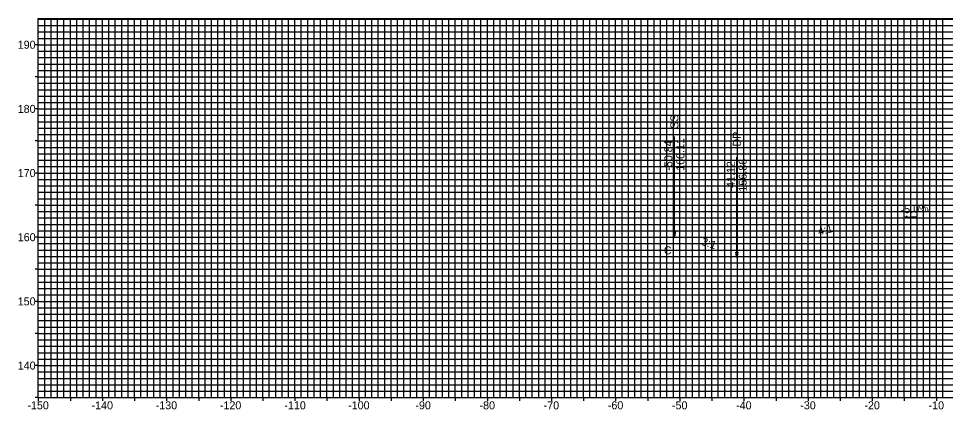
# Model space of a CAD drawing. Extents: x -153 to 153, y 133 to 194.
# Drawn here: x -153.1 to -8.6, y 133.2 to 194.1 of the extents above; entities that cross this region are included whole.
import ezdxf

# ---------------------------------------------------------------- set-up
doc = ezdxf.new("R2010")
doc.units = 0
for name, color, linetype in [('P_NCDOT_XS_Label_Grade_Point', 7, 'Continuous'), ('P_NCDOT_XS_Label_Grading_Side_Slope', 7, 'Continuous'), ('P_NCDOT_XS_Leader_Line', 7, 'Continuous'), ('P_NCDOT_XS_Sheet_Annotation_Label', 7, 'Continuous'), ('P_NCDOT_XS_Sheet_Grid_Border', 7, 'Continuous'), ('P_NCDOT_XS_Slope_Label', 7, 'Continuous'), ('P_RDY_XS_EOT_Tick_Mark', 7, 'Continuous'), ('Prop XS Label Slope Superelevation', 7, 'Continuous'), ('Sheet_Grid_Major', 7, 'Continuous'), ('Sheet_Grid_Middle', 7, 'Continuous'), ('Sheet_Grid_Minor', 7, 'Continuous')]:
    doc.layers.add(name, color=color, linetype=linetype)

msp = doc.modelspace()

# ---------------------------------------------------------------- linework, layer by layer
at = {"layer": 'P_NCDOT_XS_Leader_Line'}
for p, q in [((-50.84, 160.11), (-50.84, 175.71)), ((-41.12, 156.86), (-41.12, 172.46)), ((-41.12, 156.86), (-41.12, 172.46)), ((-50.84, 160.11), (-50.84, 169.23)), ((-41.12, 156.86), (-41.12, 165.98)), ((-41.12, 156.86), (-41.12, 165.98)), ((-50.84, 160.11), (-50.84, 161.55)), ((-41.12, 156.86), (-41.12, 158.3)), ((-41.12, 156.86), (-41.12, 158.3))]:
    msp.add_line(p, q, dxfattribs=at)
for points in [[(-50.84, 160.11), (-51.02, 160.93), (-50.67, 160.93)], [(-50.84, 160.11), (-51.02, 160.93), (-50.67, 160.93)], [(-50.84, 160.11), (-50.93, 160.52), (-50.75, 160.52)], [(-41.12, 156.86), (-41.29, 157.69), (-40.94, 157.69)], [(-41.12, 156.86), (-41.29, 157.69), (-40.94, 157.69)], [(-41.12, 156.86), (-41.29, 157.69), (-40.94, 157.69)], [(-41.12, 156.86), (-41.29, 157.69), (-40.94, 157.69)], [(-41.12, 156.86), (-41.21, 157.28), (-41.03, 157.28)], [(-41.12, 156.86), (-41.21, 157.28), (-41.03, 157.28)]]:
    msp.add_lwpolyline(points, close=True, dxfattribs=at)
at = {"layer": 'P_NCDOT_XS_Sheet_Grid_Border'}
for p, q in [((-150, 194.09), (150, 194.09)), ((-150, 135), (-150, 194.09)), ((-150, 135), (150, 135))]:
    msp.add_line(p, q, dxfattribs=at)
at = {"layer": 'P_RDY_XS_EOT_Tick_Mark'}
msp.add_line((-12, 163), (-12, 163.63), dxfattribs=at)
at = {"layer": 'Prop XS Label Slope Superelevation'}
for p, q in [((-14.9, 163.1), (-14.57, 163.36)), ((-13.1, 163.19), (-14.9, 163.1))]:
    msp.add_line(p, q, dxfattribs=at)
at = {"layer": 'Sheet_Grid_Major'}
for p, q in [((-140, 135), (-140, 194.09)), ((-130, 135), (-130, 194.09)), ((-120, 135), (-120, 194.09)), ((-110, 135), (-110, 194.09)), ((-100, 135), (-100, 194.09)), ((-90, 135), (-90, 194.09)), ((-80, 135), (-80, 194.09)), ((-70, 135), (-70, 194.09)), ((-60, 135), (-60, 194.09)), ((-50, 135), (-50, 194.09)), ((-40, 135), (-40, 194.09)), ((-30, 135), (-30, 194.09)), ((-20, 135), (-20, 194.09)), ((-10, 135), (-10, 194.09)), ((-150, 190), (150, 190)), ((-150, 180), (150, 180)), ((-150, 170), (150, 170)), ((-150, 160), (150, 160)), ((-150, 150), (150, 150)), ((-150, 140), (150, 140))]:
    msp.add_line(p, q, dxfattribs=at)
at = {"layer": 'Sheet_Grid_Middle'}
for p, q in [((-145, 135), (-145, 194.09)), ((-140, 135), (-140, 194.09)), ((-135, 135), (-135, 194.09)), ((-130, 135), (-130, 194.09)), ((-125, 135), (-125, 194.09)), ((-120, 135), (-120, 194.09)), ((-115, 135), (-115, 194.09)), ((-110, 135), (-110, 194.09)), ((-105, 135), (-105, 194.09)), ((-100, 135), (-100, 194.09)), ((-95, 135), (-95, 194.09)), ((-90, 135), (-90, 194.09)), ((-85, 135), (-85, 194.09)), ((-80, 135), (-80, 194.09)), ((-75, 135), (-75, 194.09)), ((-70, 135), (-70, 194.09)), ((-65, 135), (-65, 194.09)), ((-60, 135), (-60, 194.09)), ((-55, 135), (-55, 194.09)), ((-50, 135), (-50, 194.09)), ((-45, 135), (-45, 194.09)), ((-40, 135), (-40, 194.09)), ((-35, 135), (-35, 194.09)), ((-30, 135), (-30, 194.09)), ((-25, 135), (-25, 194.09)), ((-20, 135), (-20, 194.09)), ((-15, 135), (-15, 194.09)), ((-10, 135), (-10, 194.09)), ((-150, 190), (-150.48, 190)), ((-150, 190), (150, 190)), ((-150, 185), (-150.48, 185)), ((-150, 185), (150, 185)), ((-150, 180), (-150.48, 180)), ((-150, 180), (150, 180)), ((-150, 175), (-150.48, 175)), ((-150, 175), (150, 175)), ((-150, 170), (-150.48, 170)), ((-150, 170), (150, 170)), ((-150, 165), (-150.48, 165)), ((-150, 165), (150, 165)), ((-150, 160), (-150.48, 160)), ((-150, 160), (150, 160)), ((-150, 155), (-150.48, 155)), ((-150, 155), (150, 155)), ((-150, 150), (-150.48, 150)), ((-150, 150), (150, 150)), ((-150, 145), (-150.48, 145)), ((-150, 145), (150, 145)), ((-150, 140), (-150.48, 140)), ((-150, 140), (150, 140)), ((-150, 135), (-150.48, 135)), ((-150, 135), (-150, 134.52)), ((-145, 135), (-145, 134.52)), ((-140, 135), (-140, 134.52)), ((-135, 135), (-135, 134.52)), ((-130, 135), (-130, 134.52)), ((-125, 135), (-125, 134.52)), ((-120, 135), (-120, 134.52)), ((-115, 135), (-115, 134.52)), ((-110, 135), (-110, 134.52)), ((-105, 135), (-105, 134.52)), ((-100, 135), (-100, 134.52)), ((-95, 135), (-95, 134.52)), ((-90, 135), (-90, 134.52)), ((-85, 135), (-85, 134.52)), ((-80, 135), (-80, 134.52)), ((-75, 135), (-75, 134.52)), ((-70, 135), (-70, 134.52)), ((-65, 135), (-65, 134.52)), ((-60, 135), (-60, 134.52)), ((-55, 135), (-55, 134.52)), ((-50, 135), (-50, 134.52)), ((-45, 135), (-45, 134.52)), ((-40, 135), (-40, 134.52)), ((-35, 135), (-35, 134.52)), ((-30, 135), (-30, 134.52)), ((-25, 135), (-25, 134.52)), ((-20, 135), (-20, 134.52)), ((-15, 135), (-15, 134.52)), ((-10, 135), (-10, 134.52))]:
    msp.add_line(p, q, dxfattribs=at)
at = {"layer": 'Sheet_Grid_Minor'}
for p, q in [((-150, 194), (150, 194)), ((-149, 135), (-149, 194.09)), ((-148, 135), (-148, 194.09)), ((-147, 135), (-147, 194.09)), ((-146, 135), (-146, 194.09)), ((-144, 135), (-144, 194.09)), ((-143, 135), (-143, 194.09)), ((-142, 135), (-142, 194.09)), ((-141, 135), (-141, 194.09)), ((-139, 135), (-139, 194.09)), ((-138, 135), (-138, 194.09)), ((-137, 135), (-137, 194.09)), ((-136, 135), (-136, 194.09)), ((-134, 135), (-134, 194.09)), ((-133, 135), (-133, 194.09)), ((-132, 135), (-132, 194.09)), ((-131, 135), (-131, 194.09)), ((-129, 135), (-129, 194.09)), ((-128, 135), (-128, 194.09)), ((-127, 135), (-127, 194.09)), ((-126, 135), (-126, 194.09)), ((-124, 135), (-124, 194.09)), ((-123, 135), (-123, 194.09)), ((-122, 135), (-122, 194.09)), ((-121, 135), (-121, 194.09)), ((-119, 135), (-119, 194.09)), ((-118, 135), (-118, 194.09)), ((-117, 135), (-117, 194.09)), ((-116, 135), (-116, 194.09)), ((-114, 135), (-114, 194.09)), ((-113, 135), (-113, 194.09)), ((-112, 135), (-112, 194.09)), ((-111, 135), (-111, 194.09)), ((-109, 135), (-109, 194.09)), ((-108, 135), (-108, 194.09)), ((-107, 135), (-107, 194.09)), ((-106, 135), (-106, 194.09)), ((-104, 135), (-104, 194.09)), ((-103, 135), (-103, 194.09)), ((-102, 135), (-102, 194.09)), ((-101, 135), (-101, 194.09)), ((-99, 135), (-99, 194.09)), ((-98, 135), (-98, 194.09)), ((-97, 135), (-97, 194.09)), ((-96, 135), (-96, 194.09)), ((-94, 135), (-94, 194.09)), ((-93, 135), (-93, 194.09)), ((-92, 135), (-92, 194.09)), ((-91, 135), (-91, 194.09)), ((-89, 135), (-89, 194.09)), ((-88, 135), (-88, 194.09)), ((-87, 135), (-87, 194.09)), ((-86, 135), (-86, 194.09)), ((-84, 135), (-84, 194.09)), ((-83, 135), (-83, 194.09)), ((-82, 135), (-82, 194.09)), ((-81, 135), (-81, 194.09)), ((-79, 135), (-79, 194.09)), ((-78, 135), (-78, 194.09)), ((-77, 135), (-77, 194.09)), ((-76, 135), (-76, 194.09)), ((-74, 135), (-74, 194.09)), ((-73, 135), (-73, 194.09)), ((-72, 135), (-72, 194.09)), ((-71, 135), (-71, 194.09)), ((-69, 135), (-69, 194.09)), ((-68, 135), (-68, 194.09)), ((-67, 135), (-67, 194.09)), ((-66, 135), (-66, 194.09)), ((-64, 135), (-64, 194.09)), ((-63, 135), (-63, 194.09)), ((-62, 135), (-62, 194.09)), ((-61, 135), (-61, 194.09)), ((-59, 135), (-59, 194.09)), ((-58, 135), (-58, 194.09)), ((-57, 135), (-57, 194.09)), ((-56, 135), (-56, 194.09)), ((-54, 135), (-54, 194.09)), ((-53, 135), (-53, 194.09)), ((-52, 135), (-52, 194.09)), ((-51, 135), (-51, 194.09)), ((-49, 135), (-49, 194.09)), ((-48, 135), (-48, 194.09)), ((-47, 135), (-47, 194.09)), ((-46, 135), (-46, 194.09)), ((-44, 135), (-44, 194.09)), ((-43, 135), (-43, 194.09)), ((-42, 135), (-42, 194.09)), ((-41, 135), (-41, 194.09)), ((-39, 135), (-39, 194.09)), ((-38, 135), (-38, 194.09)), ((-37, 135), (-37, 194.09)), ((-36, 135), (-36, 194.09)), ((-34, 135), (-34, 194.09)), ((-33, 135), (-33, 194.09)), ((-32, 135), (-32, 194.09)), ((-31, 135), (-31, 194.09)), ((-29, 135), (-29, 194.09)), ((-28, 135), (-28, 194.09)), ((-27, 135), (-27, 194.09)), ((-26, 135), (-26, 194.09)), ((-24, 135), (-24, 194.09)), ((-23, 135), (-23, 194.09)), ((-22, 135), (-22, 194.09)), ((-21, 135), (-21, 194.09)), ((-19, 135), (-19, 194.09)), ((-18, 135), (-18, 194.09)), ((-17, 135), (-17, 194.09)), ((-16, 135), (-16, 194.09)), ((-14, 135), (-14, 194.09)), ((-13, 135), (-13, 194.09)), ((-12, 135), (-12, 194.09)), ((-11, 135), (-11, 194.09)), ((-9, 135), (-9, 194.09)), ((-150, 193), (150, 193)), ((-150, 192), (150, 192)), ((-150, 191), (150, 191)), ((-150, 189), (150, 189)), ((-150, 188), (150, 188)), ((-150, 187), (150, 187)), ((-150, 186), (150, 186)), ((-150, 184), (150, 184)), ((-150, 183), (150, 183)), ((-150, 182), (150, 182)), ((-150, 181), (150, 181)), ((-150, 179), (150, 179)), ((-150, 178), (150, 178)), ((-150, 177), (150, 177)), ((-150, 176), (150, 176)), ((-150, 174), (150, 174)), ((-150, 173), (150, 173)), ((-150, 172), (150, 172)), ((-150, 171), (150, 171)), ((-150, 169), (150, 169)), ((-150, 168), (150, 168)), ((-150, 167), (150, 167)), ((-150, 166), (150, 166)), ((-150, 164), (150, 164)), ((-150, 163), (150, 163)), ((-150, 162), (150, 162)), ((-150, 161), (150, 161)), ((-150, 159), (150, 159)), ((-150, 158), (150, 158)), ((-150, 157), (150, 157)), ((-150, 156), (150, 156)), ((-150, 154), (150, 154)), ((-150, 153), (150, 153)), ((-150, 152), (150, 152)), ((-150, 151), (150, 151)), ((-150, 149), (150, 149)), ((-150, 148), (150, 148)), ((-150, 147), (150, 147)), ((-150, 146), (150, 146)), ((-150, 144), (150, 144)), ((-150, 143), (150, 143)), ((-150, 142), (150, 142)), ((-150, 141), (150, 141)), ((-150, 139), (150, 139)), ((-150, 138), (150, 138)), ((-150, 137), (150, 137)), ((-150, 136), (150, 136))]:
    msp.add_line(p, q, dxfattribs=at)

# ---------------------------------------------------------------- texts
at = {"layer": 'P_NCDOT_XS_Label_Grade_Point'}
for s, p in [('-50.84', (-51.16, 170.36)), ('160.11', (-49.29, 170.36)), ('156.86', (-39.57, 167.12)), ('-41.12', (-41.44, 167.12))]:
    msp.add_text(s, height=1.248, rotation=90, dxfattribs=at).set_placement(p)
at = {"layer": 'P_NCDOT_XS_Label_Grading_Side_Slope'}
for s, p in [('SS', (-50.22, 176.91)), (' DP', (-40.49, 173.66)), (' DP', (-40.49, 173.66))]:
    msp.add_text(s, height=1.248, rotation=90, dxfattribs=at).set_placement(p)
msp.add_text('C', height=1.25, dxfattribs=at).set_placement((-52.48, 157.33))
at = {"layer": 'P_NCDOT_XS_Sheet_Annotation_Label'}
for s, p in [('190', (-153.21, 189.38)), ('180', (-153.21, 179.38)), ('170', (-153.21, 169.38)), ('160', (-153.21, 159.38)), ('150', (-153.21, 149.38)), ('140', (-153.21, 139.38)), ('-150', (-151.7, 133.18)), ('-140', (-141.7, 133.18)), ('-130', (-131.7, 133.18)), ('-120', (-121.7, 133.18)), ('-110', (-111.64, 133.18)), ('-100', (-101.7, 133.18)), ('-90', (-91.22, 133.18)), ('-80', (-81.22, 133.18)), ('-70', (-71.22, 133.18)), ('-60', (-61.22, 133.18)), ('-50', (-51.22, 133.18)), ('-40', (-41.22, 133.18)), ('-30', (-31.22, 133.18)), ('-20', (-21.22, 133.18)), ('-10', (-11.22, 133.18))]:
    msp.add_text(s, height=1.248, dxfattribs=at).set_placement(p)
at = {"layer": 'P_NCDOT_XS_Slope_Label'}
for s, rotation, p in [('-5.0%', 2.8624, (-15.54, 163.7)), ('4:1', 14.0362, (-28.31, 160.28)), ('3:1', 341.5668, (-46.74, 158.84))]:
    msp.add_text(s, height=1.248, rotation=rotation, dxfattribs=at).set_placement(p)

doc.saveas('drawing.dxf')
